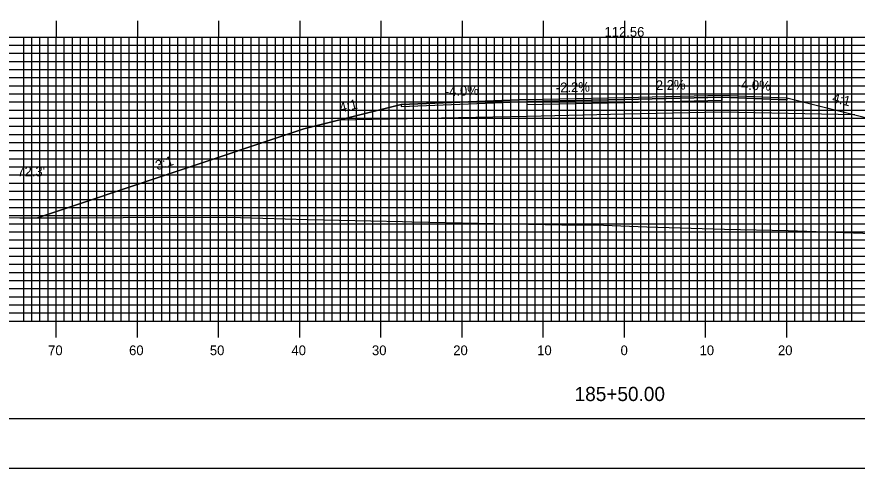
# Model space of a CAD drawing. Extents: x 1787369 to 1787713, y 442591 to 442811.
# Drawn here: x 1787460.2 to 1787563.8, y 442590.5 to 442646.2 of the extents above; entities that cross this region are included whole.
import ezdxf

# ---------------------------------------------------------------- set-up
doc = ezdxf.new("R2010")
doc.units = 0
for name, color, linetype in [('ANNOTATION', 7, 'Continuous'), ('BORDER', 7, 'Continuous'), ('D_Roadway_Centerline', 7, 'Continuous'), ('D_Roadway_Centerline_Text', 7, 'Continuous'), ('D_Roadway_Edge_Shoulder', 7, 'Continuous'), ('D_Roadway_Edge_TW', 7, 'Continuous'), ('D_Roadway_Pavement', 7, 'Continuous'), ('D_Roadway_SlopeLines', 7, 'Continuous'), ('D_Roadway_SubGrade', 7, 'Continuous'), ('D_Text_Standard', 7, 'Continuous'), ('H_V ANNOTATION', 7, 'Continuous'), ('MAJOR', 7, 'Continuous'), ('MINOR', 7, 'Continuous'), ('PLOT BOUNDARY', 7, 'Continuous'), ('S_Roadway_Centerline', 7, 'Continuous')]:
    doc.layers.add(name, color=color, linetype=linetype)

msp = doc.modelspace()

# ---------------------------------------------------------------- linework, layer by layer
at = {"layer": 'BORDER'}
msp.add_lwpolyline([(1787385.5, 442596.67), (1787705.5, 442596.67), (1787705.5, 442806.67), (1787385.5, 442806.67)], close=True, dxfattribs=at)
at = {"layer": 'D_Roadway_Centerline'}
msp.add_lwpolyline([(1787462.81, 442621.41), (1787495.6, 442632.35), (1787499.89, 442633.42), (1787507.6, 442635.35), (1787523.1, 442635.97), (1787535.1, 442636.23), (1787547.1, 442636.49), (1787555.1, 442636.17), (1787563.47, 442634.08), (1787567.1, 442633.17), (1787608.47, 442619.39)], dxfattribs=at)
at = {"layer": 'D_Roadway_Edge_Shoulder'}
for points in [[(1787523.1, 442635.97), (1787507.6, 442635.35), (1787507.6, 442635.1), (1787523.1, 442635.72)], [(1787547.1, 442636.49), (1787555.1, 442636.17), (1787555.1, 442635.92), (1787547.1, 442636.24)]]:
    msp.add_lwpolyline(points, close=True, dxfattribs=at)
at = {"layer": 'D_Roadway_Edge_TW'}
msp.add_lwpolyline([(1787523.1, 442635.72), (1787523.1, 442635.97), (1787535.1, 442636.23), (1787547.1, 442636.49), (1787547.1, 442636.24), (1787535.1, 442635.98)], close=True, dxfattribs=at)
at = {"layer": 'D_Roadway_Pavement'}
msp.add_lwpolyline([(1787523.1, 442635.3), (1787523.1, 442635.72), (1787535.1, 442635.98), (1787547.1, 442636.24), (1787547.1, 442635.83), (1787535.1, 442635.56)], close=True, dxfattribs=at)
at = {"layer": 'D_Roadway_SlopeLines'}
for points in [[(1787555.1, 442636.17), (1787567.1, 442633.17), (1787608.47, 442619.39)], [(1787507.6, 442635.35), (1787495.6, 442632.35), (1787462.81, 442621.41)]]:
    msp.add_lwpolyline(points, dxfattribs=at)
at = {"layer": 'D_Roadway_SubGrade'}
msp.add_lwpolyline([(1787523.1, 442633.88), (1787499.89, 442633.42), (1787507.6, 442635.35), (1787507.6, 442635.1), (1787523.1, 442635.72), (1787535.1, 442635.98), (1787547.1, 442636.24), (1787555.1, 442635.92), (1787555.1, 442636.17), (1787563.47, 442634.08), (1787547.1, 442634.41), (1787535.1, 442634.15)], close=True, dxfattribs=at)
at = {"layer": 'MAJOR'}
for p, q in [((1787465.1, 442645.67), (1787465.1, 442643.67)), ((1787475.1, 442645.67), (1787475.1, 442643.67)), ((1787485.1, 442645.67), (1787485.1, 442643.67)), ((1787495.1, 442645.67), (1787495.1, 442643.67)), ((1787505.1, 442645.67), (1787505.1, 442643.67)), ((1787515.1, 442645.67), (1787515.1, 442643.67)), ((1787525.1, 442645.67), (1787525.1, 442643.67)), ((1787535.1, 442645.67), (1787535.1, 442643.67)), ((1787545.1, 442645.67), (1787545.1, 442643.67)), ((1787555.1, 442645.67), (1787555.1, 442643.67)), ((1787395.1, 442643.67), (1787675.1, 442643.67)), ((1787395.1, 442643.67), (1787675.1, 442643.67)), ((1787465.1, 442608.67), (1787465.1, 442643.67)), ((1787475.1, 442608.67), (1787475.1, 442643.67)), ((1787485.1, 442608.67), (1787485.1, 442643.67)), ((1787495.1, 442608.67), (1787495.1, 442643.67)), ((1787505.1, 442608.67), (1787505.1, 442643.67)), ((1787515.1, 442608.67), (1787515.1, 442643.67)), ((1787525.1, 442608.67), (1787525.1, 442643.67)), ((1787535.1, 442608.67), (1787535.1, 442643.67)), ((1787545.1, 442608.67), (1787545.1, 442643.67)), ((1787555.1, 442608.67), (1787555.1, 442643.67)), ((1787395.1, 442638.67), (1787675.1, 442638.67)), ((1787395.1, 442633.67), (1787675.1, 442633.67)), ((1787395.1, 442628.67), (1787675.1, 442628.67)), ((1787395.1, 442623.67), (1787675.1, 442623.67)), ((1787395.1, 442618.67), (1787675.1, 442618.67)), ((1787395.1, 442613.67), (1787675.1, 442613.67)), ((1787395.1, 442608.67), (1787675.1, 442608.67)), ((1787395.1, 442608.67), (1787675.1, 442608.67)), ((1787465.1, 442606.66), (1787465.1, 442608.67)), ((1787475.1, 442606.66), (1787475.1, 442608.67)), ((1787485.1, 442606.66), (1787485.1, 442608.67)), ((1787495.1, 442606.66), (1787495.1, 442608.67)), ((1787505.1, 442606.66), (1787505.1, 442608.67)), ((1787515.1, 442606.66), (1787515.1, 442608.67)), ((1787525.1, 442606.66), (1787525.1, 442608.67)), ((1787535.1, 442606.66), (1787535.1, 442608.67)), ((1787545.1, 442606.66), (1787545.1, 442608.67)), ((1787555.1, 442606.66), (1787555.1, 442608.67))]:
    msp.add_line(p, q, dxfattribs=at)
at = {"layer": 'MINOR'}
for p, q in [((1787461.1, 442608.67), (1787461.1, 442643.67)), ((1787462.1, 442608.67), (1787462.1, 442643.67)), ((1787463.1, 442608.67), (1787463.1, 442643.67)), ((1787464.1, 442608.67), (1787464.1, 442643.67)), ((1787466.1, 442608.67), (1787466.1, 442643.67)), ((1787467.1, 442608.67), (1787467.1, 442643.67)), ((1787468.1, 442608.67), (1787468.1, 442643.67)), ((1787469.1, 442608.67), (1787469.1, 442643.67)), ((1787470.1, 442608.67), (1787470.1, 442643.67)), ((1787471.1, 442608.67), (1787471.1, 442643.67)), ((1787472.1, 442608.67), (1787472.1, 442643.67)), ((1787473.1, 442608.67), (1787473.1, 442643.67)), ((1787474.1, 442608.67), (1787474.1, 442643.67)), ((1787476.1, 442608.67), (1787476.1, 442643.67)), ((1787477.1, 442608.67), (1787477.1, 442643.67)), ((1787478.1, 442608.67), (1787478.1, 442643.67)), ((1787479.1, 442608.67), (1787479.1, 442643.67)), ((1787480.1, 442608.67), (1787480.1, 442643.67)), ((1787481.1, 442608.67), (1787481.1, 442643.67)), ((1787482.1, 442608.67), (1787482.1, 442643.67)), ((1787483.1, 442608.67), (1787483.1, 442643.67)), ((1787484.1, 442608.67), (1787484.1, 442643.67)), ((1787486.1, 442608.67), (1787486.1, 442643.67)), ((1787487.1, 442608.67), (1787487.1, 442643.67)), ((1787488.1, 442608.67), (1787488.1, 442643.67)), ((1787489.1, 442608.67), (1787489.1, 442643.67)), ((1787490.1, 442608.67), (1787490.1, 442643.67)), ((1787491.1, 442608.67), (1787491.1, 442643.67)), ((1787492.1, 442608.67), (1787492.1, 442643.67)), ((1787493.1, 442608.67), (1787493.1, 442643.67)), ((1787494.1, 442608.67), (1787494.1, 442643.67)), ((1787496.1, 442608.67), (1787496.1, 442643.67)), ((1787497.1, 442608.67), (1787497.1, 442643.67)), ((1787498.1, 442608.67), (1787498.1, 442643.67)), ((1787499.1, 442608.67), (1787499.1, 442643.67)), ((1787500.1, 442608.67), (1787500.1, 442643.67)), ((1787501.1, 442608.67), (1787501.1, 442643.67)), ((1787502.1, 442608.67), (1787502.1, 442643.67)), ((1787503.1, 442608.67), (1787503.1, 442643.67)), ((1787504.1, 442608.67), (1787504.1, 442643.67)), ((1787506.1, 442608.67), (1787506.1, 442643.67)), ((1787507.1, 442608.67), (1787507.1, 442643.67)), ((1787508.1, 442608.67), (1787508.1, 442643.67)), ((1787509.1, 442608.67), (1787509.1, 442643.67)), ((1787510.1, 442608.67), (1787510.1, 442643.67)), ((1787511.1, 442608.67), (1787511.1, 442643.67)), ((1787512.1, 442608.67), (1787512.1, 442643.67)), ((1787513.1, 442608.67), (1787513.1, 442643.67)), ((1787514.1, 442608.67), (1787514.1, 442643.67)), ((1787516.1, 442608.67), (1787516.1, 442643.67)), ((1787517.1, 442608.67), (1787517.1, 442643.67)), ((1787518.1, 442608.67), (1787518.1, 442643.67)), ((1787519.1, 442608.67), (1787519.1, 442643.67)), ((1787520.1, 442608.67), (1787520.1, 442643.67)), ((1787521.1, 442608.67), (1787521.1, 442643.67)), ((1787522.1, 442608.67), (1787522.1, 442643.67)), ((1787523.1, 442608.67), (1787523.1, 442643.67)), ((1787524.1, 442608.67), (1787524.1, 442643.67)), ((1787526.1, 442608.67), (1787526.1, 442643.67)), ((1787527.1, 442608.67), (1787527.1, 442643.67)), ((1787528.1, 442608.67), (1787528.1, 442643.67)), ((1787529.1, 442608.67), (1787529.1, 442643.67)), ((1787530.1, 442608.67), (1787530.1, 442643.67)), ((1787531.1, 442608.67), (1787531.1, 442643.67)), ((1787532.1, 442608.67), (1787532.1, 442643.67)), ((1787533.1, 442608.67), (1787533.1, 442643.67)), ((1787534.1, 442608.67), (1787534.1, 442643.67)), ((1787536.1, 442608.67), (1787536.1, 442643.67)), ((1787537.1, 442608.67), (1787537.1, 442643.67)), ((1787538.1, 442608.67), (1787538.1, 442643.67)), ((1787539.1, 442608.67), (1787539.1, 442643.67)), ((1787540.1, 442608.67), (1787540.1, 442643.67)), ((1787541.1, 442608.67), (1787541.1, 442643.67)), ((1787542.1, 442608.67), (1787542.1, 442643.67)), ((1787543.1, 442608.67), (1787543.1, 442643.67)), ((1787544.1, 442608.67), (1787544.1, 442643.67)), ((1787546.1, 442608.67), (1787546.1, 442643.67)), ((1787547.1, 442608.67), (1787547.1, 442643.67)), ((1787548.1, 442608.67), (1787548.1, 442643.67)), ((1787549.1, 442608.67), (1787549.1, 442643.67)), ((1787550.1, 442608.67), (1787550.1, 442643.67)), ((1787551.1, 442608.67), (1787551.1, 442643.67)), ((1787552.1, 442608.67), (1787552.1, 442643.67)), ((1787553.1, 442608.67), (1787553.1, 442643.67)), ((1787554.1, 442608.67), (1787554.1, 442643.67)), ((1787556.1, 442608.67), (1787556.1, 442643.67)), ((1787557.1, 442608.67), (1787557.1, 442643.67)), ((1787558.1, 442608.67), (1787558.1, 442643.67)), ((1787559.1, 442608.67), (1787559.1, 442643.67)), ((1787560.1, 442608.67), (1787560.1, 442643.67)), ((1787561.1, 442608.67), (1787561.1, 442643.67)), ((1787562.1, 442608.67), (1787562.1, 442643.67)), ((1787563.1, 442608.67), (1787563.1, 442643.67)), ((1787395.1, 442642.67), (1787675.1, 442642.67)), ((1787395.1, 442641.67), (1787675.1, 442641.67)), ((1787395.1, 442640.67), (1787675.1, 442640.67)), ((1787395.1, 442639.67), (1787675.1, 442639.67)), ((1787395.1, 442637.67), (1787675.1, 442637.67)), ((1787395.1, 442636.67), (1787675.1, 442636.67)), ((1787395.1, 442635.67), (1787675.1, 442635.67)), ((1787395.1, 442634.67), (1787675.1, 442634.67)), ((1787395.1, 442632.67), (1787675.1, 442632.67)), ((1787395.1, 442631.67), (1787675.1, 442631.67)), ((1787395.1, 442630.67), (1787675.1, 442630.67)), ((1787395.1, 442629.67), (1787675.1, 442629.67)), ((1787395.1, 442627.67), (1787675.1, 442627.67)), ((1787395.1, 442626.67), (1787675.1, 442626.67)), ((1787395.1, 442625.67), (1787675.1, 442625.67)), ((1787395.1, 442624.67), (1787675.1, 442624.67)), ((1787395.1, 442622.67), (1787675.1, 442622.67)), ((1787395.1, 442621.67), (1787675.1, 442621.67)), ((1787395.1, 442620.67), (1787675.1, 442620.67)), ((1787395.1, 442619.67), (1787675.1, 442619.67)), ((1787395.1, 442617.67), (1787675.1, 442617.67)), ((1787395.1, 442616.67), (1787675.1, 442616.67)), ((1787395.1, 442615.67), (1787675.1, 442615.67)), ((1787395.1, 442614.67), (1787675.1, 442614.67)), ((1787395.1, 442612.67), (1787675.1, 442612.67)), ((1787395.1, 442611.67), (1787675.1, 442611.67)), ((1787395.1, 442610.67), (1787675.1, 442610.67)), ((1787395.1, 442609.67), (1787675.1, 442609.67))]:
    msp.add_line(p, q, dxfattribs=at)
at = {"layer": 'PLOT BOUNDARY'}
msp.add_lwpolyline([(1787369.32, 442590.55), (1787709.32, 442590.55), (1787709.32, 442810.55), (1787369.32, 442810.55)], close=True, dxfattribs=at)
at = {"layer": 'S_Roadway_Centerline'}
msp.add_lwpolyline([(1787395.1, 442621.95), (1787401.36, 442621.92), (1787408.55, 442622.06), (1787421.06, 442622.15), (1787428.35, 442622.19), (1787446.29, 442621.67), (1787448.47, 442621.61), (1787448.84, 442621.61), (1787449.43, 442621.6), (1787460.61, 442621.41), (1787467.98, 442621.41), (1787478.74, 442621.47), (1787487.8, 442621.44), (1787496.07, 442621.17), (1787507.74, 442620.92), (1787508.9, 442620.88), (1787527.38, 442620.54), (1787531.44, 442620.51), (1787537.84, 442620.28), (1787547.42, 442619.99), (1787555.27, 442619.85), (1787566.74, 442619.43)], dxfattribs=at)

# ---------------------------------------------------------------- texts
at = {"layer": 'ANNOTATION'}
for s, rotation, p in [('-2.2%', 1.2603, (1787526.66, 442636.84)), ('2.2%', 1.2603, (1787538.98, 442637.12)), ('-4.0%', 357.7094, (1787548.9, 442637.22)), ('-4.0%', 2.2906, (1787512.99, 442636.36)), ('4:1', 14.0362, (1787500.14, 442634.34)), ('4:1', 345.9638, (1787560.61, 442635.66)), ('3:1', 18.4348, (1787477.55, 442627.23))]:
    msp.add_text(s, height=1.2, rotation=rotation, dxfattribs=at).set_placement(p)
at = {"layer": 'D_Roadway_Centerline'}
for s, p in [('C', (1787535.1, 442636.23)), ('L', (1787535.1, 442636.22))]:
    msp.add_text(s, height=0.0146, dxfattribs=at).set_placement(p)
at = {"layer": 'D_Roadway_Centerline_Text'}
msp.add_text('112.56', height=1.2, dxfattribs=at).set_placement((1787532.64, 442643.7))
at = {"layer": 'D_Text_Standard'}
msp.add_text("72.3'", height=1.2, dxfattribs=at).set_placement((1787460.31, 442626.5))
at = {"layer": 'H_V ANNOTATION'}
for s, height, p in [('70', 1.2, (1787464.11, 442604.47)), ('60', 1.2, (1787474.08, 442604.47)), ('50', 1.2, (1787484.03, 442604.47)), ('40', 1.2, (1787494.08, 442604.47)), ('30', 1.2, (1787504, 442604.47)), ('20', 1.2, (1787514.01, 442604.47)), ('10', 1.2, (1787524.35, 442604.47)), ('0', 1.2, (1787534.62, 442604.47)), ('10', 1.2, (1787544.35, 442604.47)), ('20', 1.2, (1787554.01, 442604.47)), ('185+50.00', 1.75, (1787528.96, 442598.82))]:
    msp.add_text(s, height=height, dxfattribs=at).set_placement(p)

doc.saveas('drawing.dxf')
